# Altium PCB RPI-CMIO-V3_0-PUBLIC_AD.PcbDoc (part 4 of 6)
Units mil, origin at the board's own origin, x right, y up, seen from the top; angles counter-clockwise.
Board outline 3295.4 x 4105.44 mil, 6 copper layers (TOP, GNDT, PWRT, PWRB, GNDB, BOTTOM); 114 components, 152 nets, 703 pads, 476 vias.
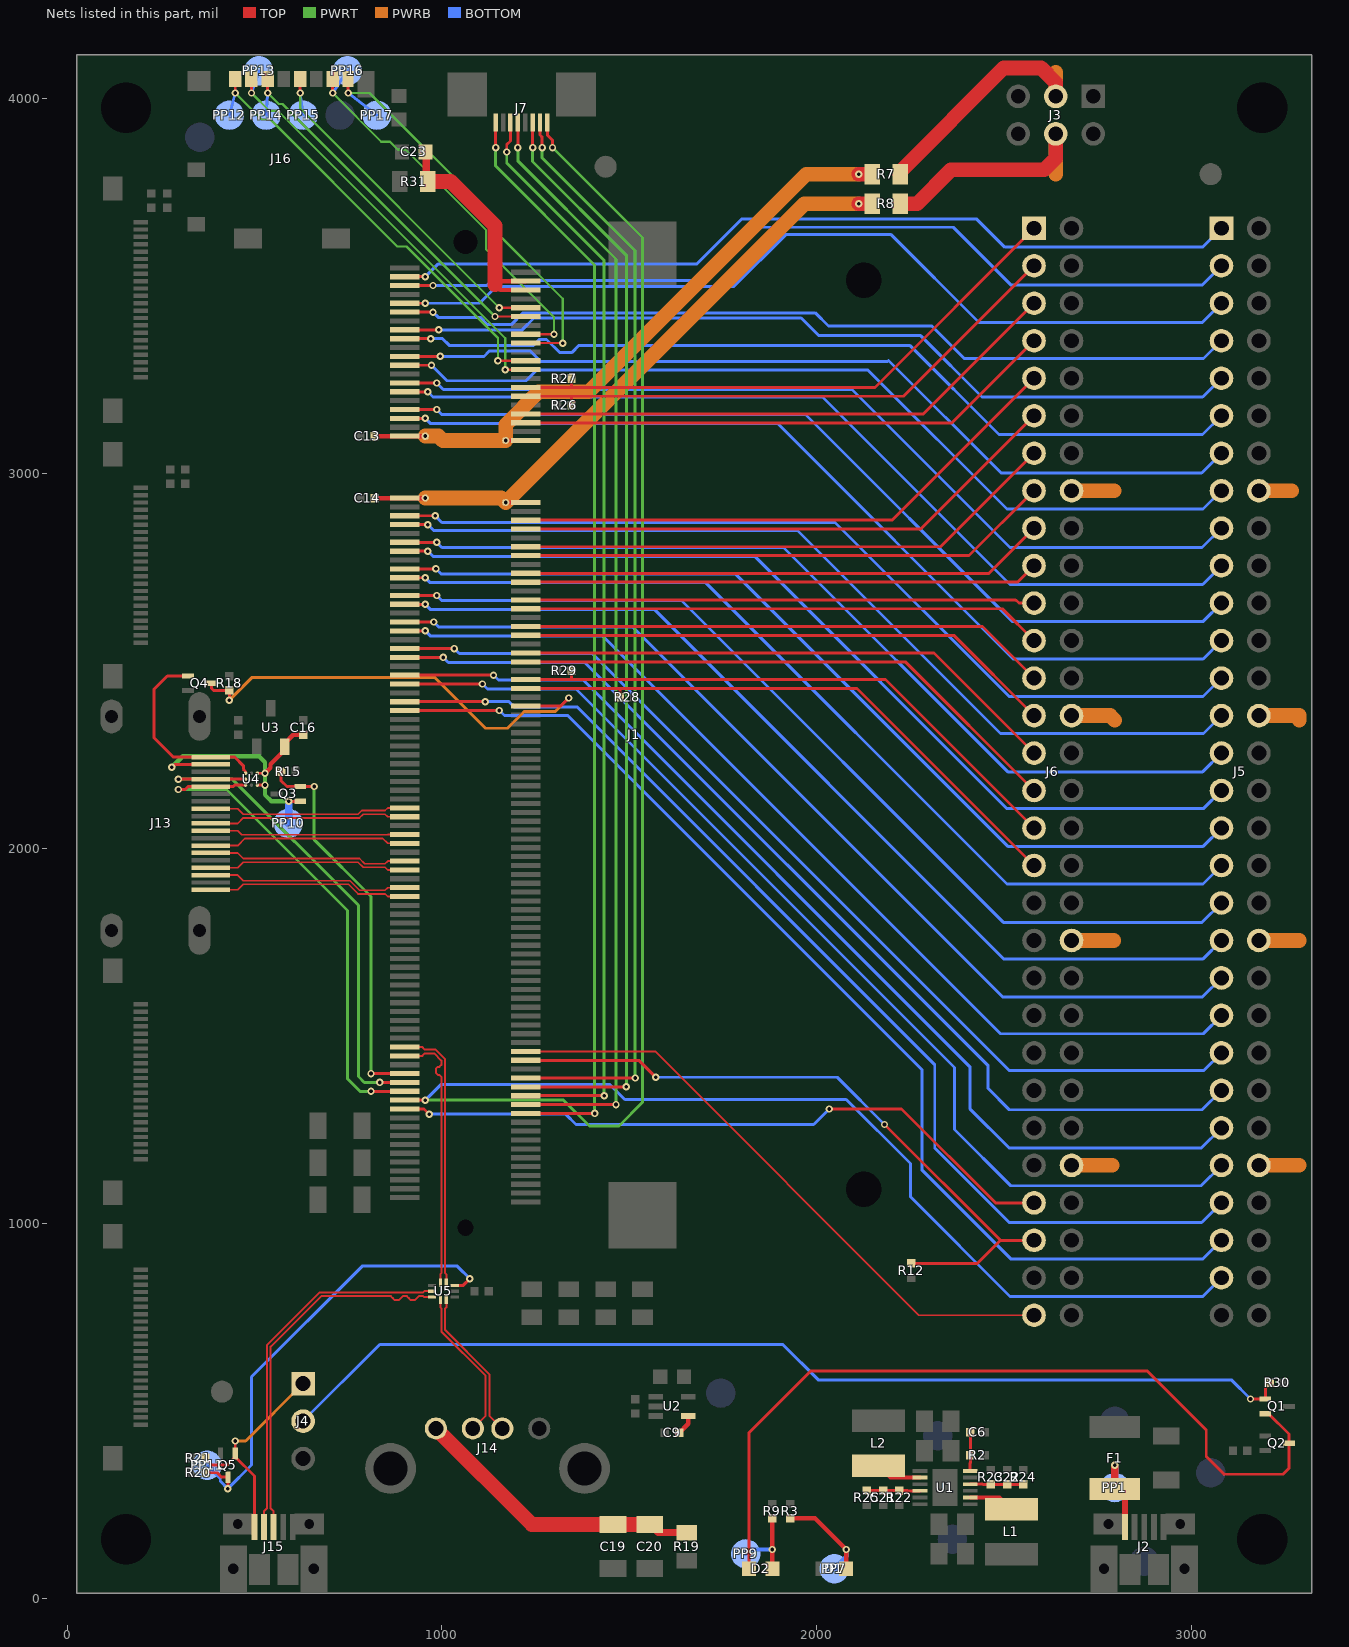
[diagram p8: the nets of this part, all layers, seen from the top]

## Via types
v1: diameter 19.68, hole 9.84, TOP to BOTTOM, 476 vias

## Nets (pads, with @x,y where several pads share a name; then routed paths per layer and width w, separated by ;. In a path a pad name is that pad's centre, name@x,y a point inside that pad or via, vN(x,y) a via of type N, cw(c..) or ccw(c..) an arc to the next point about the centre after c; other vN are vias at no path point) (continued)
GPIO0: J1.3 J5.1 | length 2293.8
  TOP w7.87: J1.3@901.58,3525.59 v1(955.79,3525.59)
  BOTTOM w7.87: v1(955.79,3525.59) 989.25,3559.05 1679.13,3559.05 1799.21,3679.13 2427.16,3679.13 2501.97,3604.33 3029.53,3604.33 J5.1@3079.92,3654.72
GPIO0-27_VREF: C13.1 J1.39 J1.40 R7.1 | length 1706.9
  TOP w11.81: C13.1@818.9,3100.39 C13.1@820.28,3100.39 J1.39@901.58,3100.39 v1(955.79,3100.39) ; v1(1170.2,3088.58) J1.40@1224.41,3088.58
  TOP w39.37: v1(2112.13,3799.21) R7.1@2147.64,3799.21
  PWRB w39.37: v1(955.79,3100.39) 991.22,3100.39 1003.03,3088.58 v1(1170.2,3088.58) 1170.2,3130.83 1257.87,3218.5 1391.73,3218.5 1972.44,3799.21 v1(2112.13,3799.21)
GPIO1: J1.5 J5.3 | length 2327.4
  TOP w7.87: J1.5@901.58,3501.97 v1(976.38,3501.97)
  BOTTOM w7.87: v1(976.38,3501.97) 1120.08,3501.97 1133.86,3515.75 1698.82,3515.75 1840.55,3657.48 2364.17,3657.48 2517.72,3503.94 3029.13,3503.94 J5.3@3079.92,3554.72
GPIO2: J1.9 J5.5 | length 2372.4
  TOP w7.87: J1.9@901.58,3454.72 v1(955.79,3454.72)
  BOTTOM w7.87: v1(955.79,3454.72) 1100.39,3454.72 1145.67,3500 1779.52,3500 ; 1779.52,3500 1917.32,3637.79 2198.82,3637.79 2433.07,3403.54 3028.74,3403.54 J5.5@3079.92,3454.72
GPIO3: J1.11 J5.7 | length 2275.5
  TOP w7.87: J1.11@901.58,3431.1 v1(976.38,3431.1)
  BOTTOM w7.87: v1(976.38,3431.1) 990.3,3417.18 1102.5,3417.18 1122.05,3397.64 1185.04,3397.64 1216.53,3429.13 1996.06,3429.13 2031.5,3393.7 2307.09,3393.7 2393.7,3307.09 3032.28,3307.09 J5.7@3079.92,3354.72
GPIO4: J1.15 J5.9 | length 2299.3
  TOP w7.87: J1.15@901.58,3383.86 v1(992.13,3383.86)
  BOTTOM w7.87: v1(992.13,3383.86) 1214.57,3383.86 1246.06,3415.35 1958.66,3415.35 2005.91,3368.11 2277.56,3368.11 2440.95,3204.72 3029.92,3204.72 J5.9@3079.92,3254.72
GPIO5: J1.17 J5.11 | length 2334.6
  TOP w7.87: J1.17@901.58,3360.24 v1(970.47,3360.24)
  BOTTOM w7.87: v1(970.47,3360.24) 1001.97,3360.24 1019.68,3342.52 1244.09,3342.52 1259.84,3358.27 1279.53,3358.27 1314.96,3322.84 1346.46,3322.84 1366.14,3342.52 2248.03,3342.52 2486.22,3104.33 3029.53,3104.33 J5.11@3079.92,3154.72
GPIO6: J1.21 J5.13 | length 2342.9
  TOP w7.87: J1.21@901.58,3312.99 v1(996.06,3312.99)
  BOTTOM w7.87: v1(996.06,3312.99) 1112.2,3312.99 1125.98,3326.77 1236.22,3326.77 1263.78,3299.21 2188.96,3299.21 2191.92,3302.17 2492.13,3001.97 3027.16,3001.97 J5.13@3079.92,3054.72
GPIO7: J1.23 J5.15 | length 2381
  TOP w7.87: J1.23@901.58,3289.37 v1(972.44,3289.37)
  BOTTOM w7.87: v1(972.44,3289.37) 1013.78,3248.03 1224.41,3248.03 1252.47,3276.09 2137.3,3276.09 2507.87,2905.51 3030.71,2905.51 J5.15@3079.92,2954.72
GPIO8: J1.27 J5.17 | length 2381.5
  TOP w7.87: J1.27@901.58,3242.13 v1(986.22,3242.13)
  BOTTOM w7.87: v1(986.22,3242.13) 1003.94,3224.41 2094.49,3224.41 2515.75,2803.15 3028.35,2803.15 J5.17@3079.92,2854.72
GPIO9: J1.29 J5.19 | length 2411.9
  TOP w7.87: J1.29@901.58,3218.5 v1(962.6,3218.5)
  BOTTOM w7.87: v1(962.6,3218.5) 976.38,3204.72 2015.75,3204.72 2515.75,2704.72 3029.92,2704.72 J5.19@3079.92,2754.72
GPIO10: J1.33 J5.21 | length 2432.4
  TOP w7.87: J1.33@901.58,3171.26 v1(986.22,3171.26)
  BOTTOM w7.87: v1(986.22,3171.26) 999.5,3157.98 1969.97,3157.98 2521.65,2606.3 3031.5,2606.3 J5.21@3079.92,2654.72
GPIO11: J1.35 J5.23 | length 2464.4
  TOP w7.87: J1.35@901.58,3147.64 v1(955.79,3147.64)
  BOTTOM w7.87: v1(955.79,3147.64) 969.07,3134.36 1895.17,3134.36 2523.62,2505.91 3031.1,2505.91 J5.23@3079.92,2554.72
GPIO12: J1.45 J5.25 | length 2398.5
  TOP w7.87: J1.45@901.58,2887.8 v1(982.28,2887.8)
  BOTTOM w7.87: v1(982.28,2887.8) 1000,2870.08 2049.21,2870.08 2513.78,2405.51 3030.71,2405.51 J5.25@3079.92,2454.72
GPIO13: J1.47 J5.27 | length 2428.8
  TOP w7.87: J1.47@901.58,2864.17 v1(962.6,2864.17)
  BOTTOM w7.87: v1(962.6,2864.17) 978.35,2848.43 1948.82,2848.43 2490.16,2307.09 3032.28,2307.09 J5.27@3079.92,2354.72
GPIO14: J1.51 J5.29 | length 2452.6
  TOP w7.87: J1.51@901.58,2816.93 v1(986.22,2816.93)
  BOTTOM w7.87: v1(986.22,2816.93) 1000,2803.15 1911.42,2803.15 2509.84,2204.72 3029.92,2204.72 J5.29@3079.92,2254.72
GPIO15: J1.53 J5.31 | length 2483
  TOP w7.87: J1.53@901.58,2793.31 v1(962.6,2793.31)
  BOTTOM w7.87: v1(962.6,2793.31) 976.38,2779.53 1834.65,2779.53 2507.87,2106.3 3031.5,2106.3 J5.31@3079.92,2154.72
GPIO16: J1.57 J5.33 | length 2505.2
  TOP w7.87: J1.57@901.58,2746.06 v1(984.25,2746.06)
  BOTTOM w7.87: v1(984.25,2746.06) 997.53,2732.78 1726.54,2732.78 1782.96,2732.79 2509.84,2005.91 3031.1,2005.91 J5.33@3079.92,2054.72
GPIO17: J1.59 J5.35 | length 2537.1
  TOP w7.87: J1.59@901.58,2722.44 v1(955.79,2722.44)
  BOTTOM w7.87: v1(955.79,2722.44) 969.07,2709.16 1704.22,2709.16 2507.87,1905.51 3030.71,1905.51 J5.35@3079.92,1954.72
GPIO18: J1.63 J5.37 | length 2560.9
  TOP w7.87: J1.63@901.58,2675.2 v1(986.22,2675.2)
  BOTTOM w7.87: v1(986.22,2675.2) 999.5,2661.92 1639.26,2661.92 2498.03,1803.15 3028.35,1803.15 J5.37@3079.92,1854.72
GPIO19: J1.65 J5.39 | length 2591.3
  TOP w7.87: J1.65@901.58,2651.58 v1(955.79,2651.58)
  BOTTOM w7.87: v1(955.79,2651.58) 969.07,2638.3 1566.43,2638.3 2500,1704.72 3029.92,1704.72 J5.39@3079.92,1754.72
GPIO20: J1.69 J5.41 | length 2613.4
  TOP w7.87: J1.69@901.58,2604.33 v1(978.35,2604.33)
  BOTTOM w7.87: v1(978.35,2604.33) 991.63,2591.05 1509.34,2591.05 2496.06,1604.33 3029.53,1604.33 J5.41@3079.92,1654.72
GPIO21: J1.71 J5.43 | length 2643.8
  TOP w7.87: J1.71@901.58,2580.71 v1(955.79,2580.71)
  BOTTOM w7.87: v1(955.79,2580.71) 969.07,2567.43 1428.63,2567.43 2490.15,1505.91 3031.1,1505.91 J5.43@3079.92,1554.72
GPIO22: J1.75 J5.45 | length 2664.3
  TOP w7.87: J1.75@901.58,2533.47 v1(1033.47,2533.47)
  BOTTOM w7.87: v1(1033.47,2533.47) 1046.74,2520.18 1401.08,2520.18 2513.78,1407.48 3032.68,1407.48 J5.45@3079.92,1454.72
GPIO23: J1.77 J5.47 | length 2735.3
  TOP w7.87: J1.77@901.58,2509.84 v1(1003.94,2509.84)
  BOTTOM w7.87: v1(1003.94,2509.84) 1017.22,2496.56 1381.39,2496.56 2457.48,1420.47 2457.48,1359.45 2513.78,1303.15 3028.35,1303.15 J5.47@3079.92,1354.72
GPIO24: J1.81 J5.49 | length 2789.1
  TOP w7.87: J1.81@901.58,2462.6 v1(1137.8,2462.6)
  BOTTOM w7.87: v1(1137.8,2462.6) 1151.08,2449.32 1377.45,2449.32 2408.66,1418.11 2408.66,1305.91 2513.78,1200.79 3025.98,1200.79 J5.49@3079.92,1254.72
GPIO25: J1.83 J5.51 | length 2852.2
  TOP w7.87: J1.83@901.58,2438.98 v1(1108.27,2438.98)
  BOTTOM w7.87: v1(1108.27,2438.98) 1121.55,2425.7 1357.77,2425.7 2367.72,1415.75 2367.72,1250.39 2517.72,1100.39 3025.59,1100.39 J5.51@3079.92,1154.72
GPIO26: J1.87 J5.53 | length 2906.2
  TOP w7.87: J1.87@901.58,2391.73 v1(1116.14,2391.73)
  BOTTOM w7.87: v1(1116.14,2391.73) 1179.13,2391.73 1192.91,2377.95 1360.24,2377.95 2314.96,1423.23 2314.96,1200.79 2513.78,1001.97 3027.16,1001.97 J5.53@3079.92,1054.72
GPIO27: J1.89 J5.55 | length 2961.4
  TOP w7.87: J1.89@901.58,2368.11 v1(1153.54,2368.11)
  BOTTOM w7.87: v1(1153.54,2368.11) 1166.82,2354.83 1336.11,2354.83 2281.5,1409.45 2281.5,1141.73 2517.72,905.51 3030.71,905.51 J5.55@3079.92,954.72
GPIO28: J1.28 J6.1 R27.1 | length 1555.5
  TOP w7.87: J1.28@1224.41,3230.32 1344.49,3230.32 ; R27.1@1345.87,3253.94 1345.87,3231.69 1344.49,3230.32 ; J6.1@2579.92,3654.72 2155.51,3230.32 1344.49,3230.32
GPIO28-45_VREF: C14.1 J1.41 J1.42 R8.1 | length 1718.1
  TOP w11.81: C14.1@818.9,2935.04 C14.1@820.28,2935.04 J1.41@901.58,2935.04 v1(955.79,2935.04) ; v1(1170.2,2923.23) J1.42@1224.41,2923.23
  TOP w39.37: v1(2112.13,3720.47) R8.1@2147.64,3720.47
  PWRB w39.37: v1(955.79,2935.04) 1158.39,2935.04 v1(1170.2,2923.23) 1967.44,3720.47 v1(2112.13,3720.47)
GPIO29: J1.30 J6.3 R26.1 | length 1523.9
  TOP w7.87: J1.30@1224.41,3206.69 1344.49,3206.69 ; R26.1@1345.87,3183.07 1345.87,3205.32 1344.49,3206.69 ; J6.3@2579.92,3554.72 2231.89,3206.69 1344.49,3206.69
GPIO30: J1.34 J6.5 | length 1477.8
  TOP w7.87: J1.34@1224.41,3159.45 2284.65,3159.45 J6.5@2579.92,3454.72
GPIO31: J1.36 J6.7 | length 1446.2
  TOP w7.87: J1.36@1224.41,3135.83 2361.02,3135.83 J6.7@2579.92,3354.72
GPIO32: J1.46 J6.9 | length 1512.4
  TOP w7.87: J1.46@1224.41,2875.98 2201.18,2875.98 J6.9@2579.92,3254.72
GPIO33: J1.48 J6.11 | length 1480.8
  TOP w7.87: J1.48@1224.41,2852.36 2277.56,2852.36 J6.11@2579.92,3154.72
GPIO34: J1.52 J6.13 | length 1458.9
  TOP w7.87: J1.52@1224.41,2805.12 2330.32,2805.12 J6.13@2579.92,3054.72
GPIO35: J1.54 J6.15 | length 1427.3
  TOP w7.87: J1.54@1224.41,2781.5 2406.69,2781.5 J6.15@2579.92,2954.72
GPIO36: J1.58 J6.17 | length 1405.4
  TOP w7.87: J1.58@1224.41,2734.25 2459.45,2734.25 J6.17@2579.92,2854.72
GPIO37: J1.60 J6.19 | length 1373.8
  TOP w7.87: J1.60@1224.41,2710.63 2535.83,2710.63 J6.19@2579.92,2754.72
GPIO38: J1.64 J6.21 | length 1359.1
  TOP w7.87: J1.64@1224.41,2663.39 2530.83,2663.39 2539.49,2654.72 J6.21@2579.92,2654.72
GPIO39: J1.66 J6.23 | length 1390.7
  TOP w7.87: J1.66@1224.41,2639.76 2494.88,2639.76 J6.23@2579.92,2554.72
GPIO40: J1.70 J6.25 | length 1412.6
  TOP w7.87: J1.70@1224.41,2592.52 2442.13,2592.52 J6.25@2579.92,2454.72
GPIO41: J1.72 J6.27 | length 1444.2
  TOP w7.87: J1.72@1224.41,2568.9 2365.75,2568.9 J6.27@2579.92,2354.72
GPIO42: J1.76 J6.29 | length 1466.1
  TOP w7.87: J1.76@1224.41,2521.65 2312.99,2521.65 J6.29@2579.92,2254.72
GPIO43: J1.78 J6.31 | length 1497.7
  TOP w7.87: J1.78@1224.41,2498.03 2236.61,2498.03 J6.31@2579.92,2154.72
GPIO44: J1.82 J6.33 R29.1 | length 1543.4
  TOP w7.87: J1.82@1224.41,2450.79 1346.46,2450.79 ; R29.1@1345.87,2474.41 1345.87,2451.38 1346.46,2450.79 ; J6.33@2579.92,2054.72 2183.86,2450.79 1346.46,2450.79
GPIO45: J1.84 J6.35 R28.1 | length 1575.1
  TOP w7.87: J1.84@1224.41,2427.16 1474.41,2427.16 ; R28.1@1475,2403.54 1475,2426.58 1474.41,2427.16 ; J6.35@2579.92,1954.72 2107.48,2427.16 1474.41,2427.16
H5V: C16.1 J13.18 PP10.1 Q3.1 U3.2 U4.A1 U4.C1 | length 823.3
  TOP w7.87: v1(279.53,2216.53) 287.4,2224.41 J13.18@383.47,2224.41 ; U4.A1@507.87,2169.29 v1(528.23,2169.29) ; U4.C1@507.87,2200.79 v1(528.23,2200.79) ; v1(591.46,2125.98) Q3.1@622.05,2125.98
  TOP w11.81: v1(528.23,2200.79) 542.9,2215.46 542.9,2224.99 580.71,2262.8 U3.2@580.71,2271.65 580.71,2280.51 603.94,2303.74 C16.1@629.92,2303.74
  PWRT w11.81: v1(279.53,2216.53) 309.06,2246.06 512.48,2246.06 528.23,2230.32 v1(528.23,2200.79) v1(528.23,2169.29) 528.23,2143.03 545.28,2125.98 v1(591.46,2125.98)
  BOTTOM w19.68: PP10.1@590.55,2066.93 591.46,2067.84 v1(591.46,2125.98)
HDMI_CEC: J1.171 Q3.2 R15.1 | length 1037.6
  TOP w7.87: R15.1@571.46,2204.72 571.46,2180.51 586.61,2165.35 Q3.2@622.05,2165.35 v1(659.45,2165.35) ; v1(811.02,1399.61) J1.171@901.58,1399.61
  PWRT w7.87: v1(659.45,2165.35) 659.45,2023.62 811.02,1872.05 v1(811.02,1399.61)
HDMI_CK_N: J1.111 J13.12 | length 531.1
  TOP w4.57: J13.12@383.47,2106.3 455.31,2106.3 470.05,2091.55 776.4,2091.55 786.24,2101.4 848.48,2101.4 855.35,2108.27 J1.111@901.58,2108.27
HDMI_CK_P: J1.113 J13.10 | length 531.1
  TOP w4.57: J13.10@383.47,2066.93 455.31,2066.93 470.05,2081.67 780.49,2081.67 790.34,2091.52 848.48,2091.52 855.35,2084.65 J1.113@901.58,2084.65
HDMI_D0_N: J1.117 J13.9 | length 522.7
  TOP w4.57: J13.9@383.47,2047.24 455.31,2047.24 465.71,2036.84 854.79,2036.84 855.35,2037.4 J1.117@901.58,2037.4
HDMI_D0_P: J1.119 J13.7 | length 531.5
  TOP w4.57: J13.7@383.47,2007.87 455.31,2007.87 474.39,2026.96 842.17,2026.96 855.35,2013.78 J1.119@901.58,2013.78
HDMI_D1_N: J1.123 J13.6 | length 532.8
  TOP w4.57: J13.6@383.47,1988.19 455.31,1988.19 470.05,1973.45 780.49,1973.45 794.27,1959.66 848.48,1959.66 855.35,1966.53 J1.123@901.58,1966.53
HDMI_D1_P: J1.125 J13.4 | length 532.8
  TOP w4.57: J13.4@383.47,1948.82 455.31,1948.82 470.05,1963.56 776.4,1963.56 790.18,1949.78 848.48,1949.78 855.35,1942.91 J1.125@901.58,1942.91
HDMI_D2_N: J1.129 J13.3 | length 537.7
  TOP w4.57: J13.3@383.47,1929.13 455.31,1929.13 470.05,1914.39 754.9,1914.39 780.49,1888.8 848.48,1888.8 855.35,1895.67 J1.129@901.58,1895.67
HDMI_D2_P: J1.131 J13.1 | length 537.7
  TOP w4.57: J13.1@383.47,1889.76 455.31,1889.76 470.05,1904.51 750.81,1904.51 776.4,1878.92 848.48,1878.92 855.35,1872.05 J1.131@901.58,1872.05
HDMI_HPD: J13.19 Q4.1 U4.C3 | length 526.8
  TOP w7.87: Q4.1@322.84,2460.63 267.72,2460.63 232.28,2425.2 232.28,2295.28 283.47,2244.1 J13.19@383.47,2244.1 447.52,2244.1 470.47,2221.14 470.47,2211.63 476.38,2205.72 U4.C3@476.38,2200.79
HDMI_HPD_N_1V8: J1.88 Q4.3 R18.2 | length 1233.1
  TOP w7.87: Q4.3@385.83,2440.95 385.83,2427.16 390.94,2422.05 433.07,2422.05 R18.2@433.07,2421.85 v1(433.07,2395.67) ; J1.88@1224.41,2379.92 1316.93,2379.92 v1(1338.58,2401.58)
  PWRB w7.87: v1(433.07,2395.67) 494.09,2456.69 980.31,2456.69 1116.14,2320.87 1175.2,2320.87 1220.47,2366.14 1303.15,2366.14 v1(1338.58,2401.58)
HDMI_SCL: J1.175 J13.15 U4.A3 | length 1384.8
  TOP w7.87: v1(297.24,2157.48) 315.47,2157.48 323.35,2165.35 J13.15@383.47,2165.35 443.58,2165.35 447.52,2169.29 U4.A3@476.38,2169.29 ; v1(811.02,1352.36) J1.175@901.58,1352.36
  PWRT w7.87: v1(297.24,2157.48) 425.2,2157.48 748.03,1834.65 748.03,1385.83 781.5,1352.36 v1(811.02,1352.36)
HDMI_SDA: J1.173 J13.16 U4.B3 | length 1386.1
  TOP w7.87: v1(297.24,2185.04) J13.16@383.47,2185.04 U4.B3@476.38,2185.04 ; v1(834.65,1375.98) J1.173@901.58,1375.98
  PWRT w7.87: v1(297.24,2185.04) 440.94,2185.04 777.56,1848.43 777.56,1391.73 793.31,1375.98 v1(834.65,1375.98)
N1195355: D2.2 PP9.1 R9.2 | length 210.4
  TOP w11.81: D2.2@1881.89,78.74 v1(1881.89,129.92) R9.2@1881.89,213.19 R9.2@1881.89,213.39
  BOTTOM w11.81: PP9.1@1811.02,118.11 1822.84,129.92 v1(1881.89,129.92)
N1195439: D2.1 Q1.2 Q2.3 | length 2210.8
  TOP w7.87: D2.1@1818.9,78.74 1818.9,440.94 1984.25,606.3 2881.89,606.3 3039.37,448.82 3039.37,377.95 3086.61,330.71 3244.09,330.71 3259.84,346.46 Q2.3@3259.84,413.39 3259.84,437.99 3205.71,492.13 Q1.2@3196.85,492.13
N1202496: C6.1 R2.2 U1.12 | length 103.6
  TOP w7.87: U1.12@2409.45,339.57 2409.45,359.96 2410.04,360.55 R2.2@2410.04,381.89 C6.1@2410.04,442.91
N1202592: L1.1 U1.8 | length 123.3
  TOP w9.84: U1.8@2409.45,268.7 2488.19,268.7 L1.1@2519.68,237.21
N1202604: L2.1 U1.2 | length 123.3
  TOP w9.84: L2.1@2165.35,353.35 2196.85,321.85 U1.2@2275.59,321.85
N1202780: F1.1 J2.1 PP1.1 | length 234.8
  TOP w15.75: F1.1@2795.28,291.34 2822.84,263.78 J2.1@2822.84,189.96
  TOP w19.68: F1.1@2795.28,291.34 v1(2795.28,354.33)
  BOTTOM w19.68: PP1.1@2795.28,295.28 v1(2795.28,354.33)
N1203166: C9.1 U2.4 | length 55.3
  TOP w11.81: C9.1@1633.27,440.94 1657.48,465.16 U2.4@1657.48,486.22
N1203318: D1.2 PP7.1 R3.2 | length 299.5
  TOP w11.81: R3.2@1929.13,213.19 1995.47,213.19 v1(2078.74,129.92) D1.2@2078.74,78.74
  BOTTOM w11.81: PP7.1@2047.24,78.74 2078.74,110.24 v1(2078.74,129.92)
N1313759: C21.2 R22.2 R25.1 U1.4 | length 141.9
  TOP w7.87: R25.1@2133.86,286.81 C21.2@2177.16,286.81 R22.2@2220.47,286.81 2241.73,286.81 2242.13,286.42 U1.4@2275.59,286.42
N1313939: C22.2 R23.2 R24.1 U1.10 | length 141.9
  TOP w7.87: U1.10@2409.45,304.13 2442.91,304.13 2443.31,303.74 R23.2@2464.57,303.74 C22.2@2507.87,303.74 R24.1@2551.18,303.74
N1329395: PP11.1 Q5.3 R20.2 U5.10 | length 1271.4
  TOP w7.87: R20.2@369.29,334.65 R20.2@369.49,334.65 400.59,334.65 412.4,322.84 Q5.3@429.13,322.84 v1(429.13,292.24) ; U5.10@1034.25,834.65 1057.09,834.65 v1(1074.8,852.36)
  BOTTOM w7.87: PP11.1@374.02,354.33 408.82,319.53 408.82,312.56 v1(429.13,292.24) 492.13,355.24 492.13,590.55 787.4,885.83 1041.34,885.83 v1(1074.8,852.36)
N1357591: J4.2 Q1.1 R30.1 | length 2760.5
  TOP w7.87: v1(3157.48,531.5) Q1.1@3196.85,531.5 3196.85,562.4 R30.1@3209.25,574.8
  BOTTOM w7.87: J4.2@629.92,472.44 834.65,677.16 1909.45,677.16 2003.94,582.68 3106.3,582.68 v1(3157.48,531.5)
RUN: J1.177 J5.57 J7.1 | length 5855.6
  TOP w7.87: J1.177@901.58,1328.74 v1(955.79,1328.74) ; J7.1@1281.5,3937.01 1281.5,3903.54 1295.28,3889.76 v1(1295.28,3870.08)
  PWRT w7.87: v1(955.79,1328.74) 1324.8,1328.74 1393.7,1259.84 1472.44,1259.84 1535.43,1322.84 1535.43,3629.92 v1(1295.28,3870.08)
  BOTTOM w7.87: v1(955.79,1328.74) 997.13,1370.08 1448.82,1370.08 1488.19,1330.71 2078.74,1330.71 2250,1159.45 2250,1070.87 2515.75,805.12 3030.32,805.12 J5.57@3079.92,854.72
SDX_CLK: J1.10 J16.5 PP15.1 | length 960.9
  TOP w5.91: v1(1153.54,3442.91) J1.10@1224.41,3442.91
  TOP w7.87: J16.5@621.85,4053.15 622.05,4052.95 v1(622.05,4015.75)
  PWRT w5.91: v1(622.05,4015.75) 622.05,3974.41 v1(1153.54,3442.91)
  BOTTOM w7.87: v1(622.05,4015.75) PP15.1@629.92,3956.69
SDX_CMD: J1.12 J16.3 PP14.1 | length 1032.8
  TOP w5.91: v1(1141.73,3419.29) J1.12@1224.41,3419.29
  TOP w7.87: J16.3@535.24,4053.15 535.43,4052.95 v1(535.43,4015.75)
  PWRT w5.91: v1(535.43,4015.75) 564.96,3986.22 574.8,3986.22 v1(1141.73,3419.29)
  BOTTOM w7.87: PP14.1@531.5,3956.69 531.5,3975.87 533.47,3986.22 v1(535.43,4015.75)
SDX_D0: J1.16 J16.7 PP16.1 | length 1096.9
  TOP w5.91: J1.16@1224.41,3372.05 v1(1299.21,3372.05)
  TOP w7.87: J16.7@708.47,4053.15 708.66,4052.95 v1(708.66,4015.75)
  PWRT w5.91: v1(708.66,4015.75) 838.58,3885.83 861.61,3885.83 883.27,3864.17 903.54,3864.17 1118.11,3649.61 1118.11,3598.42 1299.21,3417.32 v1(1299.21,3372.05)
  BOTTOM w7.87: v1(708.66,4015.75) PP16.1@748.03,4074.8
SDX_D1: J1.18 J16.8 PP17.1 | length 1170.8
  TOP w5.91: J1.18@1224.41,3348.42 v1(1322.84,3348.42)
  TOP w7.87: J16.8@749.8,4053.15 750,4052.95 v1(750,4015.75)
  PWRT w5.91: v1(750,4015.75) 807.09,4015.75 1149.61,3673.23 1149.61,3639.76 1322.84,3466.54 v1(1322.84,3348.42)
  BOTTOM w7.87: v1(750,4015.75) PP17.1@826.77,3956.69
SDX_D2: J1.22 J16.1 PP12.1 | length 1205.9
  TOP w5.91: v1(1149.61,3301.18) J1.22@1224.41,3301.18
  TOP w7.87: J16.1@448.62,4053.15 448.82,4052.95 v1(448.82,4015.75)
  PWRT w5.91: v1(448.82,4015.75) 519.68,3944.88 542.72,3944.88 881.3,3606.3 905.51,3606.3 1149.61,3362.2 v1(1149.61,3301.18)
  BOTTOM w7.87: PP12.1@433.07,3956.69 v1(448.82,4015.75)
SDX_D3: J1.24 J16.2 PP13.1 | length 1187
  TOP w5.91: v1(1169.29,3277.56) J1.24@1224.41,3277.56
  TOP w7.87: J16.2@491.93,4053.15 492.13,4052.95 v1(492.13,4015.75)
  PWRT w5.91: v1(492.13,4015.75) 539.37,3968.5 562.4,3968.5 1169.29,3361.61 v1(1169.29,3277.56)
  BOTTOM w7.87: v1(492.13,4015.75) PP13.1@511.81,4074.8
SDX_VREF: C23.1 J1.4 J1.6 R31.1 | length 641.9
  TOP w11.81: J1.6@1224.41,3490.16 1155.51,3490.16 1141.73,3503.94 1151.58,3513.78 J1.4@1224.41,3513.78
  TOP w19.68: C23.1@956.69,3858.27 958.66,3856.3 958.66,3783.46 R31.1@962.6,3779.53
  TOP w39.37: R31.1@962.6,3779.53 1023.62,3779.53 1141.73,3661.42 1141.73,3503.94
TVDAC: J1.166 J6.59 | length 1647.1
  TOP w4.92: J1.166@1224.41,1458.66 1568.9,1458.66 2272.84,754.72 J6.59@2579.92,754.72
USB_DM: J1.167 U5.2 | length 719.3
  TOP w5.35: J1.167@901.58,1446.85 947.96,1446.85 954.83,1453.72 979.35,1453.72 999,1434.08 999,1422.82 993.64,1417.46 989.61,1417.46 984.25,1412.11 984.25,1401.4 989.61,1396.04 993.64,1396.04 999,1390.69 999,867.11 996.06,864.17 U5.2@996.06,841.34
USB_DP: J1.165 U5.1 | length 720.7
  TOP w5.35: J1.165@901.58,1470.47 947.96,1470.47 954.83,1463.6 983.44,1463.6 1008.88,1438.17 1008.88,867.11 1011.81,864.17 U5.1@1011.81,839.37
USB_OTGID: J1.168 J6.55 R12.2 | length 1818.2
  TOP w7.87: J1.168@1224.41,1435.04 1525.59,1435.04 v1(1570.87,1389.76) ; v1(2181.1,1263.78) 2490.16,954.72 ; R12.2@2251.97,893.11 2428.54,893.11 2490.16,954.72 ; J6.55@2579.92,954.72 2490.16,954.72
  BOTTOM w7.87: v1(1570.87,1389.76) 2055.12,1389.76 v1(2181.1,1263.78)
USBA_DM: J14.2 U5.6 | length 408.1
  TOP w5.35: U5.6@996.06,796.46 996.06,776 999,773.06 999,711.44 1117.11,593.33 1117.11,487.18 J14.2@1082.68,452.76
USBA_DP: J14.3 U5.7 | length 408.1
  TOP w5.35: U5.7@1011.81,796.46 1011.81,776 1008.88,773.06 1008.88,715.53 1126.99,597.42 1126.99,487.18 J14.3@1161.42,452.76
USBB_DM: J15.2 U5.4 | length 988.2
  TOP w5.35: J15.2@525.59,189.96 525.59,231.42 533.44,239.28 533.44,675.18 674.23,815.97 950.23,815.97 953.16,818.9 U5.4@973.62,818.9
USBB_DP: J15.3 U5.5 | length 989.9
  TOP w5.35: J15.3@551.18,189.96 551.18,231.42 543.33,239.28 543.33,671.08 678.33,806.08 864.01,806.08 869.36,800.73 869.36,800.63 874.72,795.28 885.42,795.28 890.78,800.63 890.78,800.73 896.13,806.08 906.84,806.08 912.2,800.73 912.2,800.63 917.55,795.28 928.26,795.28 933.61,800.63 933.61,800.73 938.97,806.08 950.23,806.08 953.16,803.15 U5.5@973.62,803.15
VBUSA: C19.1 C20.1 J14.1 R19.2 | length 784.3
  TOP w19.68: C20.1@1555.12,196.85 1576.77,175.2 R19.2@1653.54,175.2
  TOP w39.37: J14.1@984.25,452.76 1240.16,196.85 C19.1@1456.69,196.85 C20.1@1555.12,196.85
VBUSB: J4.1 J15.1 Q5.1 R21.1 | length 591.7
  TOP w7.87: R21.1@369.49,374.02 369.49,372.84 386.84,355.49 427.34,355.49 Q5.1@448.82,376.97 ; v1(448.82,419.29) Q5.1@448.82,385.83 Q5.1@448.82,376.97 ; J15.1@500,189.96 500,325.79 Q5.1@448.82,376.97
  PWRB w7.87: v1(448.82,419.29) 476.77,419.29 J4.1@629.92,572.44
VC_TCK: J1.180 J7.8 | length 2936.2
  TOP w7.87: v1(1143.7,3870.08) J7.8@1143.7,3937.01 ; J1.180@1224.41,1293.31 v1(1407.62,1293.31)
  PWRT w7.87: v1(1143.7,3870.08) 1143.7,3820.87 1407.62,3556.95 v1(1407.62,1293.31)
VC_TDI: J1.174 J7.3 | length 2944.1
  TOP w7.87: J1.174@1224.41,1364.17 v1(1492.13,1364.17) ; v1(1242.13,3870.08) J7.3@1242.13,3937.01
  PWRT w7.87: v1(1242.13,3870.08) 1242.13,3832.68 1492.13,3582.68 v1(1492.13,1364.17)
VC_TDO: J1.178 J7.5 | length 2968.7
  TOP w7.87: v1(1202.76,3870.08) J7.5@1202.76,3937.01 ; J1.178@1224.41,1316.93 v1(1464.57,1316.93)
  PWRT w7.87: v1(1202.76,3870.08) 1202.76,3834.65 1464.57,3572.84 v1(1464.57,1316.93)
VC_TMS: J1.176 J7.6 | length 2916.8
  TOP w7.87: v1(1173.23,3858.27) 1173.23,3877.95 1183.07,3887.79 J7.6@1183.07,3937.01 ; J1.176@1224.41,1340.55 v1(1433.07,1340.55)
  PWRT w7.87: v1(1173.23,3858.27) 1173.23,3828.74 1433.07,3568.9 v1(1433.07,1340.55)
VC_TRST_N: J1.172 J7.2 | length 2945.7
  TOP w7.87: J1.172@1224.41,1387.8 v1(1515.75,1387.8) ; J7.2@1261.81,3937.01 1261.81,3903.54 1267.72,3897.64 v1(1267.72,3870.08)
  PWRT w7.87: v1(1267.72,3870.08) 1267.72,3842.52 1515.75,3594.49 v1(1515.75,1387.8)
VDD_CORE: J1.179 J6.53 | length 1816.3
  TOP w7.87: J1.179@901.58,1305.12 952.76,1305.12 v1(966.54,1291.34) ; v1(2033.47,1305.12) 2226.38,1305.12 2476.77,1054.72 J6.53@2579.92,1054.72
  BOTTOM w7.87: v1(966.54,1291.34) 1330.71,1291.34 1358.27,1263.78 1992.13,1263.78 v1(2033.47,1305.12)
VG0: J3.3 J5.16 J5.28 J5.40 J5.52 R7.2 | length 1076.3
  TOP w39.37: R7.2@2222.44,3799.21 2222.44,3806.1 2499.02,4082.68 2598.43,4082.68 2637.8,4043.31 J3.3@2637.8,4006.69
  PWRB w39.37: J3.3@2637.8,4006.69 2637.8,4070.87 ; J5.52@3179.92,1154.72 3287.4,1154.72 ; J5.40@3179.92,1754.72 3287.4,1754.72 ; J5.28@3179.92,2354.72 3287.4,2354.72 3287.4,2342.52 ; J5.16@3179.92,2954.72 3267.72,2954.72
VG1: J3.4 J6.16 J6.28 J6.40 J6.52 R8.2 | length 1093.2
  TOP w39.37: R8.2@2222.44,3720.47 2267.8,3720.47 2358.35,3811.02 2607.36,3811.02 2637.8,3841.46 J3.4@2637.8,3906.69
  PWRB w39.37: 2637.8,3799.21 J3.4@2637.8,3906.69 ; J6.52@2679.92,1154.72 2788.58,1154.72 ; J6.40@2679.92,1754.72 2792.52,1754.72 ; J6.28@2679.92,2354.72 2783.07,2354.72 2795.28,2342.52 ; J6.16@2679.92,2954.72 2793.31,2954.72
pads on no net: Designator1. J1. J1.124 J1.126 J1.128 J1.130 J1.132 J1.154 J1.156 J1.158 J1.160 J1.162 J2. J2.2 J2.3 J2.4 J5.59 J7. J9. J9.11 J9.12 J9.14 J9.15 J10. J10.11 J10.12 J10.14 J10.15 J10.17 J10.18 J11. J12. J12.17 J12.18 J13.14 J15. J15.4 J16.9 J16.10 U1.5 U1.11 U4.B1

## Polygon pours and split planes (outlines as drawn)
N1357591 on TOP "TOP-N1357591" (solid, pour order 1000): 3168.61,528.71 ccw(c3165.83,531.5) 3168.61,534.28 3164.44,538.45 3156.5,531.5 3164.44,524.54 3168.61,528.71 ccw(c3165.83,531.5)
N1329395 on TOP "TOP-N1329395" (solid, pour order 1001): 431.92,303.38 ccw(c429.13,300.59) 426.35,303.38 422.18,299.21 429.13,291.26 436.09,299.21 431.92,303.38 ccw(c429.13,300.59)
N1329395 on TOP "TOP-N1329395 1" (solid, pour order 1002): 1064.96,846.46 ccw(c1068.9,846.46) 1068.9,842.52 1074.8,842.52 1075.5,853.06 1064.96,852.36 1064.96,846.46 ccw(c1068.9,846.46)
DSI1_DP0 on TOP "TOP-DSI1_DP0" (solid, pour order 1003): 588.58,3296.4 ccw(c590.87,3296.4) 590.87,3294.12 598.42,3294.12 598.83,3304.37 588.58,3303.96 588.58,3296.4 ccw(c590.87,3296.4)
DSI1_DP0 on TOP "TOP-DSI1_DP0 1" (solid, pour order 1004): 1311.38,2305.16 ccw(c1313.64,2305.16) 1313.64,2302.9 1321.22,2302.9 1321.62,2313.15 1311.38,2312.74 1311.38,2305.16 ccw(c1313.64,2305.16)
DSI0_DN1 on TOP "TOP-DSI0_DN1" (solid, pour order 1005): 276.72,2521.37 ccw(c275.11,2522.98) 276.72,2524.6 271.38,2529.94 263.85,2522.98 271.38,2516.02 276.72,2521.37 ccw(c275.11,2522.98)
DSI0_DN1 on TOP "TOP-DSI0_DN1 1" (solid, pour order 1006): 747.72,2315.77 ccw(c747.72,2318.05) 750,2318.05 750,2325.61 739.75,2326.02 740.16,2315.77 747.72,2315.77 ccw(c747.72,2318.05)
CD0_SDA on TOP "TOP-CD0_SDA" (solid, pour order 1007): 89.87,853.52 ccw(c87.09,856.3) 89.87,859.08 85.7,863.26 77.76,856.3 85.7,849.34 89.87,853.52 ccw(c87.09,856.3)
CD0_SDA on TOP "TOP-CD0_SDA 1" (solid, pour order 1008): 87.91,2940.13 ccw(c85.12,2942.91) 87.91,2945.7 83.73,2949.87 75.79,2942.91 83.73,2935.96 87.91,2940.13 ccw(c85.12,2942.91)
CD0_SCL on TOP "TOP-CD0_SCL" (solid, pour order 1009): 120.08,824.8 ccw(c116.14,824.8) 116.14,828.74 110.24,828.74 109.54,818.2 120.08,818.9 120.08,824.8 ccw(c116.14,824.8)
CD0_SCL on TOP "TOP-CD0_SCL 1" (solid, pour order 1010): 104.33,2909.45 ccw(c100.39,2909.45) 100.39,2913.39 94.49,2913.39 93.79,2902.85 104.33,2903.54 104.33,2909.45 ccw(c100.39,2909.45)
HDMI_HPD_N_1V8 on TOP "TOP-HDMI_HPD_N_1V8" (solid, pour order 1011): 435.85,2406.8 ccw(c433.07,2404.02) 430.29,2406.8 426.11,2402.63 433.07,2394.68 440.03,2402.63 435.85,2406.8 ccw(c433.07,2404.02)
HDMI_HPD_N_1V8 on TOP "TOP-HDMI_HPD_N_1V8 1" (solid, pour order 1012): 1328.74,2395.67 ccw(c1332.68,2395.67) 1332.68,2391.73 1338.58,2391.73 1339.28,2402.27 1328.74,2401.58 1328.74,2395.67 ccw(c1332.68,2395.67)
N1203318 on TOP "TOP-N1203318" (solid, pour order 1013): 2074.56,120.18 ccw(c2078.74,124.35) 2082.92,120.18 2085.7,122.97 2078.74,131.4 2071.78,122.97 2074.56,120.18 ccw(c2078.74,124.35)
N1203318 on TOP "TOP-N1203318 1" (solid, pour order 1014): 2074.8,139.76 ccw(c2074.8,133.86) 2068.9,133.86 2068.9,129.92 2079.78,128.88 2078.74,139.76 2074.8,139.76 ccw(c2074.8,133.86)
HDMI_SCL on TOP "TOP-HDMI_SCL" (solid, pour order 1015): 308.38,2154.7 ccw(c305.59,2157.48) 308.38,2160.26 304.21,2164.44 296.26,2157.48 304.21,2150.52 308.38,2154.7 ccw(c305.59,2157.48)
HDMI_SCL on TOP "TOP-HDMI_SCL 1" (solid, pour order 1016): 822.16,1349.58 ccw(c819.37,1352.36) 822.16,1355.15 817.98,1359.32 810.04,1352.36 817.98,1345.41 822.16,1349.58 ccw(c819.37,1352.36)
HDMI_SDA on TOP "TOP-HDMI_SDA" (solid, pour order 1017): 308.38,2182.26 ccw(c305.59,2185.04) 308.38,2187.82 304.21,2192 296.26,2185.04 304.21,2178.08 308.38,2182.26 ccw(c305.59,2185.04)
HDMI_SDA on TOP "TOP-HDMI_SDA 1" (solid, pour order 1018): 845.78,1373.2 ccw(c843,1375.98) 845.78,1378.77 841.61,1382.94 833.66,1375.98 841.61,1369.03 845.78,1373.2 ccw(c843,1375.98)
N1195355 on TOP "TOP-N1195355" (solid, pour order 1019): 1877.71,120.18 ccw(c1881.89,124.35) 1886.07,120.18 1888.85,122.97 1881.89,131.4 1874.93,122.97 1877.71,120.18 ccw(c1881.89,124.35)
N1195355 on TOP "TOP-N1195355 1" (solid, pour order 1020): 1886.07,139.66 ccw(c1881.89,135.49) 1877.71,139.66 1874.93,136.88 1881.89,128.44 1888.85,136.88 1886.07,139.66 ccw(c1881.89,135.49)
DAC_2V5 on TOP "TOP-DAC_2V5" (solid, pour order 1021): 1669.47,594.73 ccw(c1673.65,590.55) 1669.47,586.37 1672.26,583.6 1680.69,590.55 1672.26,597.51 1669.47,594.73 ccw(c1673.65,590.55)
VBUSB on TOP "TOP-VBUSB" (solid, pour order 1022): 446.04,408.16 ccw(c448.82,410.94) 451.6,408.16 455.78,412.33 448.82,420.28 441.86,412.33 446.04,408.16 ccw(c448.82,410.94)
5V on TOP "TOP-5V" (solid, pour order 1023): 452.52,2357.85 ccw(c456.69,2362.03) 460.87,2357.85 463.65,2360.64 456.69,2369.08 449.74,2360.64 452.52,2357.85 ccw(c456.69,2362.03)
5V on TOP "TOP-5V 1" (solid, pour order 1024): 2278.37,242.35 ccw(c2275.59,239.57) 2272.81,242.35 2268.63,238.18 2275.59,230.24 2282.55,238.18 2278.37,242.35 ccw(c2275.59,239.57)
5V on TOP "TOP-5V 2" (solid, pour order 1025): 2445.25,397.8 ccw(c2448.03,400.59) 2450.82,397.8 2454.99,401.98 2448.03,409.92 2441.08,401.98 2445.25,397.8 ccw(c2448.03,400.59)
CAM0_IO1 on TOP "TOP-CAM0_IO1" (solid, pour order 1026): 166.65,794.46 ccw(c163.86,797.24) 166.65,800.03 162.47,804.2 154.53,797.24 162.47,790.29 166.65,794.46 ccw(c163.86,797.24)
CAM0_IO0 on TOP "TOP-CAM0_IO0" (solid, pour order 1027): 155.51,761.81 ccw(c151.58,761.81) 151.58,765.75 145.67,765.75 144.97,755.21 155.51,755.9 155.51,761.81 ccw(c151.58,761.81)
GND on TOP "TOP-GND" (solid, pour order 1028): 220.24,583.49 ccw(c223.03,580.71) 220.24,577.92 224.42,573.75 232.36,580.71 224.42,587.66 220.24,583.49 ccw(c223.03,580.71)
GND on TOP "TOP-GND 1" (solid, pour order 1029): 220.24,524.44 ccw(c223.03,521.65) 220.24,518.87 224.42,514.7 232.36,521.65 224.42,528.61 220.24,524.44 ccw(c223.03,521.65)
GND on TOP "TOP-GND 2" (solid, pour order 1030): 220.24,465.38 ccw(c223.03,462.6) 220.24,459.82 224.42,455.64 232.36,462.6 224.42,469.56 220.24,465.38 ccw(c223.03,462.6)
GND on TOP "TOP-GND 3" (solid, pour order 1031): 220.24,760.66 ccw(c223.03,757.87) 220.24,755.09 224.42,750.92 232.36,757.87 224.42,764.83 220.24,760.66 ccw(c223.03,757.87)
GND on TOP "TOP-GND 4" (solid, pour order 1032): 173.46,696.04 ccw(c170.67,698.82) 173.46,701.6 169.28,705.78 161.34,698.82 169.28,691.86 173.46,696.04 ccw(c170.67,698.82)
GND on TOP "TOP-GND 5" (solid, pour order 1033): 220.24,642.55 ccw(c223.03,639.76) 220.24,636.98 224.42,632.81 232.36,639.76 224.42,646.72 220.24,642.55 ccw(c223.03,639.76)
GND on TOP "TOP-GND 6" (solid, pour order 1034): 220.24,819.71 ccw(c223.03,816.93) 220.24,814.15 224.42,809.97 232.36,816.93 224.42,823.89 220.24,819.71 ccw(c223.03,816.93)
GND on TOP "TOP-GND 7" (solid, pour order 1035): 220.24,1292.15 ccw(c223.03,1289.37) 220.24,1286.59 224.42,1282.41 232.36,1289.37 224.42,1296.33 220.24,1292.15 ccw(c223.03,1289.37)
GND on TOP "TOP-GND 8" (solid, pour order 1036): 220.24,1233.1 ccw(c223.03,1230.32) 220.24,1227.53 224.42,1223.36 232.36,1230.32 224.42,1237.27 220.24,1233.1 ccw(c223.03,1230.32)
GND on TOP "TOP-GND 9" (solid, pour order 1037): 220.24,1174.04 ccw(c223.03,1171.26) 220.24,1168.48 224.42,1164.3 232.36,1171.26 224.42,1178.22 220.24,1174.04 ccw(c223.03,1171.26)
GND on TOP "TOP-GND 10" (solid, pour order 1038): 220.24,1469.32 ccw(c223.03,1466.53) 220.24,1463.75 224.42,1459.58 232.36,1466.53 224.42,1473.49 220.24,1469.32 ccw(c223.03,1466.53)
GND on TOP "TOP-GND 11" (solid, pour order 1039): 220.24,1410.26 ccw(c223.03,1407.48) 220.24,1404.7 224.42,1400.52 232.36,1407.48 224.42,1414.44 220.24,1410.26 ccw(c223.03,1407.48)
GND on TOP "TOP-GND 12" (solid, pour order 1040): 220.24,1351.21 ccw(c223.03,1348.43) 220.24,1345.64 224.42,1341.47 232.36,1348.43 224.42,1355.38 220.24,1351.21 ccw(c223.03,1348.43)
GND on TOP "TOP-GND 13" (solid, pour order 1041): 220.24,1528.37 ccw(c223.03,1525.59) 220.24,1522.81 224.42,1518.63 232.36,1525.59 224.42,1532.55 220.24,1528.37 ccw(c223.03,1525.59)
GND on TOP "TOP-GND 14" (solid, pour order 1042): 220.24,2552 ccw(c223.03,2549.21) 220.24,2546.43 224.42,2542.26 232.36,2549.21 224.42,2556.17 220.24,2552 ccw(c223.03,2549.21)
GND on TOP "TOP-GND 15" (solid, pour order 1043): 220.24,2611.05 ccw(c223.03,2608.27) 220.24,2605.48 224.42,2601.31 232.36,2608.27 224.42,2615.22 220.24,2611.05 ccw(c223.03,2608.27)
GND on TOP "TOP-GND 16" (solid, pour order 1044): 220.24,2670.11 ccw(c223.03,2667.32) 220.24,2664.54 224.42,2660.37 232.36,2667.32 224.42,2674.28 220.24,2670.11 ccw(c223.03,2667.32)
GND on TOP "TOP-GND 17" (solid, pour order 1045): 220.24,2729.16 ccw(c223.03,2726.38) 220.24,2723.6 224.42,2719.42 232.36,2726.38 224.42,2733.34 220.24,2729.16 ccw(c223.03,2726.38)
GND on TOP "TOP-GND 18" (solid, pour order 1046): 220.24,2788.22 ccw(c223.03,2785.43) 220.24,2782.65 224.42,2778.48 232.36,2785.43 224.42,2792.39 220.24,2788.22 ccw(c223.03,2785.43)
GND on TOP "TOP-GND 19" (solid, pour order 1047): 220.24,2847.27 ccw(c223.03,2844.49) 220.24,2841.7 224.42,2837.53 232.36,2844.49 224.42,2851.45 220.24,2847.27 ccw(c223.03,2844.49)
GND on TOP "TOP-GND 20" (solid, pour order 1048): 220.24,2906.33 ccw(c223.03,2903.54) 220.24,2900.76 224.42,2896.59 232.36,2903.54 224.42,2910.5 220.24,2906.33 ccw(c223.03,2903.54)
GND on TOP "TOP-GND 21" (solid, pour order 1049): 220.24,3260.66 ccw(c223.03,3257.87) 220.24,3255.09 224.42,3250.92 232.36,3257.87 224.42,3264.83 220.24,3260.66 ccw(c223.03,3257.87)
GND on TOP "TOP-GND 22" (solid, pour order 1050): 220.24,3437.82 ccw(c223.03,3435.04) 220.24,3432.26 224.42,3428.08 232.36,3435.04 224.42,3442 220.24,3437.82 ccw(c223.03,3435.04)
GND on TOP "TOP-GND 23" (solid, pour order 1051): 220.24,3378.77 ccw(c223.03,3375.98) 220.24,3373.2 224.42,3369.03 232.36,3375.98 224.42,3382.94 220.24,3378.77 ccw(c223.03,3375.98)
GND on TOP "TOP-GND 24" (solid, pour order 1052): 220.24,3319.71 ccw(c223.03,3316.93) 220.24,3314.15 224.42,3309.97 232.36,3316.93 224.42,3323.89 220.24,3319.71 ccw(c223.03,3316.93)
GND on TOP "TOP-GND 25" (solid, pour order 1053): 220.24,3555.93 ccw(c223.03,3553.15) 220.24,3550.37 224.42,3546.19 232.36,3553.15 224.42,3560.11 220.24,3555.93 ccw(c223.03,3553.15)
GND on TOP "TOP-GND 26" (solid, pour order 1054): 220.24,3496.88 ccw(c223.03,3494.09) 220.24,3491.31 224.42,3487.14 232.36,3494.09 224.42,3501.05 220.24,3496.88 ccw(c223.03,3494.09)
GND on TOP "TOP-GND 27" (solid, pour order 1055): 220.24,3614.99 ccw(c223.03,3612.21) 220.24,3609.42 224.42,3605.25 232.36,3612.21 224.42,3619.16 220.24,3614.99 ccw(c223.03,3612.21)
GND on TOP "TOP-GND 28" (solid, pour order 1056): 316.57,371.23 ccw(c313.78,374.02) 316.57,376.8 312.39,380.97 304.45,374.02 312.39,367.06 316.57,371.23 ccw(c313.78,374.02)
GND on TOP "TOP-GND 29" (solid, pour order 1057): 406.66,405.28 ccw(c409.45,408.07) 412.23,405.28 416.41,409.46 409.45,417.4 402.49,409.46 406.66,405.28 ccw(c409.45,408.07)
GND on TOP "TOP-GND 30" (solid, pour order 1058): 328.58,1906.66 ccw(c325.79,1909.45) 328.58,1912.23 324.4,1916.41 316.46,1909.45 324.4,1902.49 328.58,1906.66 ccw(c325.79,1909.45)
GND on TOP "TOP-GND 31" (solid, pour order 1059): 328.58,1965.72 ccw(c325.79,1968.5) 328.58,1971.29 324.4,1975.46 316.46,1968.5 324.4,1961.55 328.58,1965.72 ccw(c325.79,1968.5)
GND on TOP "TOP-GND 32" (solid, pour order 1060): 328.58,2024.78 ccw(c325.79,2027.56) 328.58,2030.34 324.4,2034.52 316.46,2027.56 324.4,2020.6 328.58,2024.78 ccw(c325.79,2027.56)
GND on TOP "TOP-GND 33" (solid, pour order 1061): 438.35,1912.23 ccw(c441.14,1909.45) 438.35,1906.66 442.53,1902.49 450.47,1909.45 442.53,1916.41 438.35,1912.23 ccw(c441.14,1909.45)
GND on TOP "TOP-GND 34" (solid, pour order 1062): 438.35,2030.34 ccw(c441.14,2027.56) 438.35,2024.78 442.53,2020.6 450.47,2027.56 442.53,2034.52 438.35,2030.34 ccw(c441.14,2027.56)
GND on TOP "TOP-GND 35" (solid, pour order 1063): 438.35,1971.29 ccw(c441.14,1968.5) 438.35,1965.72 442.53,1961.55 450.47,1968.5 442.53,1975.46 438.35,1971.29 ccw(c441.14,1968.5)
GND on TOP "TOP-GND 36" (solid, pour order 1064): 328.58,2201.94 ccw(c325.79,2204.72) 328.58,2207.51 324.4,2211.68 316.46,2204.72 324.4,2197.77 328.58,2201.94 ccw(c325.79,2204.72)
GND on TOP "TOP-GND 37" (solid, pour order 1065): 328.58,2083.83 ccw(c325.79,2086.61) 328.58,2089.4 324.4,2093.57 316.46,2086.61 324.4,2079.66 328.58,2083.83 ccw(c325.79,2086.61)
GND on TOP "TOP-GND 38" (solid, pour order 1066): 438.35,2089.4 ccw(c441.14,2086.61) 438.35,2083.83 442.53,2079.66 450.47,2086.61 442.53,2093.57 438.35,2089.4 ccw(c441.14,2086.61)
GND on TOP "TOP-GND 39" (solid, pour order 1067): 438.35,2207.51 ccw(c441.14,2204.72) 438.35,2201.94 442.53,2197.77 450.47,2204.72 442.53,2211.68 438.35,2207.51 ccw(c441.14,2204.72)
GND on TOP "TOP-GND 40" (solid, pour order 1068): 283.47,2403.54 ccw(c279.53,2403.54) 279.53,2407.48 273.62,2407.48 272.92,2396.94 283.47,2397.64 283.47,2403.54 ccw(c279.53,2403.54)
GND on TOP "TOP-GND 41" (solid, pour order 1069): 489.34,2210.01 ccw(c492.13,2212.79) 494.91,2210.01 499.08,2214.18 492.13,2222.13 485.17,2214.18 489.34,2210.01 ccw(c492.13,2212.79)
GND on TOP "TOP-GND 42" (solid, pour order 1070): 460.87,2287.82 ccw(c456.69,2283.64) 452.52,2287.82 449.74,2285.03 456.69,2276.6 463.65,2285.03 460.87,2287.82 ccw(c456.69,2283.64)
GND on TOP "TOP-GND 43" (solid, pour order 1071): 501.73,2298.41 ccw(c505.91,2302.58) 510.08,2298.41 512.86,2301.19 505.91,2309.63 498.95,2301.19 501.73,2298.41 ccw(c505.91,2302.58)
GND on TOP "TOP-GND 44" (solid, pour order 1072): 787.64,2917.74 ccw(c783.47,2913.56) 779.29,2917.74 776.51,2914.95 783.47,2906.52 790.42,2914.95 787.64,2917.74 ccw(c783.47,2913.56)
GND on TOP "TOP-GND 45" (solid, pour order 1073): 779.29,3117.7 ccw(c783.47,3121.87) 787.64,3117.7 790.42,3120.48 783.47,3128.92 776.51,3120.48 779.29,3117.7 ccw(c783.47,3121.87)
GND on TOP "TOP-GND 46" (solid, pour order 1074): 946.04,1120.32 ccw(c950.22,1116.14) 946.04,1111.97 948.83,1109.18 957.26,1116.14 948.83,1123.1 946.04,1120.32 ccw(c950.22,1116.14)
GND on TOP "TOP-GND 47" (solid, pour order 1075): 946.04,1214.81 ccw(c950.22,1210.63) 946.04,1206.45 948.83,1203.67 957.26,1210.63 948.83,1217.59 946.04,1214.81 ccw(c950.22,1210.63)
GND on TOP "TOP-GND 48" (solid, pour order 1076): 857.11,1277.32 ccw(c852.93,1281.5) 857.11,1285.67 854.32,1288.45 845.89,1281.5 854.32,1274.54 857.11,1277.32 ccw(c852.93,1281.5)
GND on TOP "TOP-GND 49" (solid, pour order 1077): 857.11,1489.92 ccw(c852.93,1494.09) 857.11,1498.27 854.32,1501.05 845.89,1494.09 854.32,1487.14 857.11,1489.92 ccw(c852.93,1494.09)
GND on TOP "TOP-GND 50" (solid, pour order 1078): 857.11,1419.05 ccw(c852.93,1423.23) 857.11,1427.41 854.32,1430.18 845.89,1423.23 854.32,1416.27 857.11,1419.05 ccw(c852.93,1423.23)
GND on TOP "TOP-GND 51" (solid, pour order 1079): 857.11,1631.65 ccw(c852.93,1635.83) 857.11,1640 854.32,1642.78 845.89,1635.83 854.32,1628.87 857.11,1631.65 ccw(c852.93,1635.83)
GND on TOP "TOP-GND 52" (solid, pour order 1080): 857.11,1560.78 ccw(c852.93,1564.96) 857.11,1569.14 854.32,1571.92 845.89,1564.96 854.32,1558 857.11,1560.78 ccw(c852.93,1564.96)
GND on TOP "TOP-GND 53" (solid, pour order 1081): 857.11,1844.25 ccw(c852.93,1848.43) 857.11,1852.6 854.32,1855.38 845.89,1848.43 854.32,1841.47 857.11,1844.25 ccw(c852.93,1848.43)
GND on TOP "TOP-GND 54" (solid, pour order 1082): 857.11,1773.38 ccw(c852.93,1777.56) 857.11,1781.74 854.32,1784.52 845.89,1777.56 854.32,1770.6 857.11,1773.38 ccw(c852.93,1777.56)
GND on TOP "TOP-GND 55" (solid, pour order 1083): 857.11,1702.52 ccw(c852.93,1706.69) 857.11,1710.87 854.32,1713.65 845.89,1706.69 854.32,1699.74 857.11,1702.52 ccw(c852.93,1706.69)
GND on TOP "TOP-GND 56" (solid, pour order 1084): 857.11,1985.98 ccw(c852.93,1990.16) 857.11,1994.34 854.32,1997.11 845.89,1990.16 854.32,1983.2 857.11,1985.98 ccw(c852.93,1990.16)
GND on TOP "TOP-GND 57" (solid, pour order 1085): 857.11,1915.11 ccw(c852.93,1919.29) 857.11,1923.47 854.32,1926.25 845.89,1919.29 854.32,1912.34 857.11,1915.11 ccw(c852.93,1919.29)
GND on TOP "TOP-GND 58" (solid, pour order 1086): 857.11,2127.71 ccw(c852.93,2131.89) 857.11,2136.07 854.32,2138.85 845.89,2131.89 854.32,2124.93 857.11,2127.71 ccw(c852.93,2131.89)
GND on TOP "TOP-GND 59" (solid, pour order 1087): 857.11,2056.85 ccw(c852.93,2061.02) 857.11,2065.2 854.32,2067.98 845.89,2061.02 854.32,2054.07 857.11,2056.85 ccw(c852.93,2061.02)
GND on TOP "TOP-GND 60" (solid, pour order 1088): 857.11,2198.58 ccw(c852.93,2202.76) 857.11,2206.93 854.32,2209.71 845.89,2202.76 854.32,2195.8 857.11,2198.58 ccw(c852.93,2202.76)
GND on TOP "TOP-GND 61" (solid, pour order 1089): 857.11,2340.31 ccw(c852.93,2344.49) 857.11,2348.66 854.32,2351.45 845.89,2344.49 854.32,2337.53 857.11,2340.31 ccw(c852.93,2344.49)
GND on TOP "TOP-GND 62" (solid, pour order 1090): 857.11,2269.45 ccw(c852.93,2273.62) 857.11,2277.8 854.32,2280.58 845.89,2273.62 854.32,2266.66 857.11,2269.45 ccw(c852.93,2273.62)
GND on TOP "TOP-GND 63" (solid, pour order 1091): 857.11,2552.91 ccw(c852.93,2557.09) 857.11,2561.26 854.32,2564.04 845.89,2557.09 854.32,2550.13 857.11,2552.91 ccw(c852.93,2557.09)
GND on TOP "TOP-GND 64" (solid, pour order 1092): 857.11,2482.04 ccw(c852.93,2486.22) 857.11,2490.4 854.32,2493.18 845.89,2486.22 854.32,2479.26 857.11,2482.04 ccw(c852.93,2486.22)
GND on TOP "TOP-GND 65" (solid, pour order 1093): 857.11,2411.18 ccw(c852.93,2415.35) 857.11,2419.53 854.32,2422.31 845.89,2415.35 854.32,2408.4 857.11,2411.18 ccw(c852.93,2415.35)
GND on TOP "TOP-GND 66" (solid, pour order 1094): 857.11,2694.64 ccw(c852.93,2698.82) 857.11,2703 854.32,2705.78 845.89,2698.82 854.32,2691.86 857.11,2694.64 ccw(c852.93,2698.82)
GND on TOP "TOP-GND 67" (solid, pour order 1095): 857.11,2623.78 ccw(c852.93,2627.95) 857.11,2632.13 854.32,2634.91 845.89,2627.95 854.32,2621 857.11,2623.78 ccw(c852.93,2627.95)
GND on TOP "TOP-GND 68" (solid, pour order 1096): 857.11,2765.51 ccw(c852.93,2769.68) 857.11,2773.86 854.32,2776.64 845.89,2769.68 854.32,2762.73 857.11,2765.51 ccw(c852.93,2769.68)
GND on TOP "TOP-GND 69" (solid, pour order 1097): 857.11,2836.37 ccw(c852.93,2840.55) 857.11,2844.73 854.32,2847.51 845.89,2840.55 854.32,2833.6 857.11,2836.37 ccw(c852.93,2840.55)
GND on TOP "TOP-GND 70" (solid, pour order 1098): 857.11,2907.24 ccw(c852.93,2911.42) 857.11,2915.6 854.32,2918.37 845.89,2911.42 854.32,2904.46 857.11,2907.24 ccw(c852.93,2911.42)
GND on TOP "TOP-GND 71" (solid, pour order 1099): 857.11,3119.84 ccw(c852.93,3124.02) 857.11,3128.19 854.32,3130.97 845.89,3124.02 854.32,3117.06 857.11,3119.84 ccw(c852.93,3124.02)
GND on TOP "TOP-GND 72" (solid, pour order 1100): 857.11,3190.71 ccw(c852.93,3194.88) 857.11,3199.06 854.32,3201.84 845.89,3194.88 854.32,3187.92 857.11,3190.71 ccw(c852.93,3194.88)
